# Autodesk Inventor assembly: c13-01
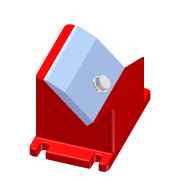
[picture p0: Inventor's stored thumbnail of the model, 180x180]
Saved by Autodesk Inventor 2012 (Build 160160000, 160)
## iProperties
Created: 2010-11
Part Number: c13-01
Document SubType Name: Assembly
Designer: Beta-8540w
Author: Beta-8540w
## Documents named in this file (5)
- C:\Users\VMuser\Desktop\Inventor 2012 Essentials\Assemblies\Chapter 13\c13-01.iam
- C:\Users\VMuser\Desktop\Inventor 2012 Essentials\Content Center Files\en-US\ISO 4017\ISO 4017 - M10 x 35ISO.ipt
- C:\Users\VMuser\Desktop\Inventor 2012 Essentials\Parts\Chapter 13\c13-01.ipt
- C:\Users\VMuser\Desktop\Inventor 2012 Essentials\Parts\Chapter 13\c13-02.ipt
- C:\Users\VMuser\Desktop\Inventor 2012 Essentials\Content Center Files\en-US\ISO 7091\ISO 7091 - ST 10 - 100 HV.ipt
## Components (4 placed, 4 different names)
1. c13-01:1 — Insert:1, Angle:1
2. c13-02:1 — Insert:1, Angle:1, Insert:2
3. ISO 4017 M10 x 35:1 — Insert:3
4. ISO 7091 ST 10 - 100 HV:1 — Insert:2, Insert:3
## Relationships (4: Insert 3, Angle 1)
- Insert:1: c13-01:1 ↔ c13-02:1
- Angle:1: c13-01:1 ↔ c13-02:1
- Insert:2: c13-02:1 ↔ ISO 7091 ST 10 - 100 HV:1
- Insert:3: ISO 4017 M10 x 35:1 ↔ ISO 7091 ST 10 - 100 HV:1
